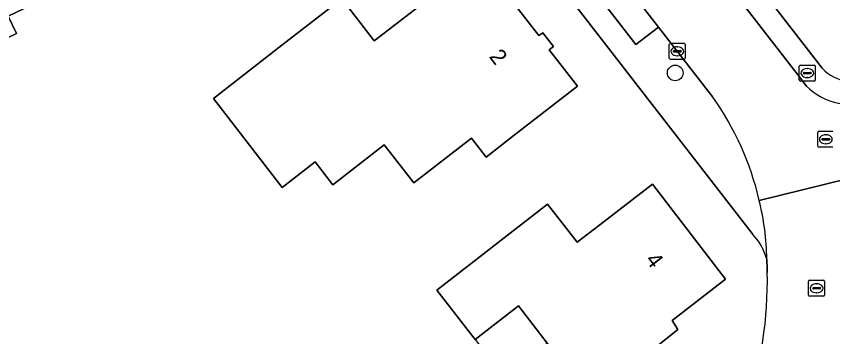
# Model space of a CAD drawing. Extents: x 159499 to 160349, y 382524 to 383273.
# Drawn here: x 159751.6 to 159802.6, y 382906.1 to 382926.1 of the extents above; entities that cross this region are included whole.
import ezdxf

# ---------------------------------------------------------------- set-up
doc = ezdxf.new("R2010")
doc.units = 0
for name, color, linetype in [('IMGEO_Boom', 7, 'Continuous'), ('IMGEO_Brandkraan', 7, 'Continuous'), ('IMGEO_Erf', 7, 'Continuous'), ('IMGEO_Kolk', 7, 'Continuous'), ('IMGEO_Pand', 7, 'Continuous'), ('IMGEO_Pand_nummerreeks', 7, 'Continuous'), ('IMGEO_Pand_overbouw', 7, 'Continuous'), ('IMGEO_Parkeervlak_open', 7, 'Continuous'), ('IMGEO_Rijbaan_lokaal_open', 7, 'Continuous'), ('IMGEO_Rioolput', 7, 'Continuous'), ('IMGEO_Voetpad_open', 7, 'Continuous')]:
    doc.layers.add(name, color=color, linetype=linetype)

msp = doc.modelspace()

# ---------------------------------------------------------------- linework, layer by layer
at = {"layer": 'IMGEO_Boom'}
msp.add_circle((159792.767, 382922.58), 0.489, dxfattribs=at)
at = {"layer": 'IMGEO_Brandkraan'}
for p, q in [((159800.523, 382922.147), (159800.523, 382922.999)), ((159800.598, 382923.073), (159801.45, 382923.073)), ((159800.825, 382922.616), (159801.223, 382922.616)), ((159801.011, 382922.853), (159801.036, 382922.853)), ((159801.524, 382922.999), (159801.524, 382922.147)), ((159800.782, 382922.567), (159800.782, 382922.579)), ((159801.22, 382922.53), (159800.822, 382922.53)), ((159801.034, 382922.293), (159801.009, 382922.293)), ((159801.266, 382922.579), (159801.266, 382922.567)), ((159801.45, 382922.073), (159800.598, 382922.073))]:
    msp.add_line(p, q, dxfattribs=at)
for points in [[(159800.523, 382922.147), (159800.523, 382922.999)], [(159800.598, 382923.073), (159801.45, 382923.073)], [(159801.524, 382922.999), (159801.524, 382922.147)], [(159801.45, 382922.073), (159800.598, 382922.073)]]:
    msp.add_lwpolyline(points, dxfattribs=at)
for centre, radius, start, end in [((159800.6, 382922.997), 0.0765, 91.552, 178.448), ((159800.6, 382922.997), 0.0765, 91.552, 178.448), ((159800.822, 382922.576), 0.0403, 85.8775, 175.7526), ((159801.227, 382922.578), 0.0386, 1.7309, 96.639), ((159801.448, 382922.997), 0.0765, 1.552, 88.448), ((159801.448, 382922.997), 0.0765, 1.552, 88.448), ((159800.6, 382922.149), 0.0765, 181.552, 268.448), ((159800.6, 382922.149), 0.0765, 181.552, 268.448), ((159800.819, 382922.566), 0.0366, 178.938, 274.7102), ((159801.223, 382922.573), 0.043, 264.8664, 352.4533), ((159801.448, 382922.149), 0.0765, 271.552, 358.448), ((159801.448, 382922.149), 0.0765, 271.552, 358.448)]:
    msp.add_arc(centre, radius, start, end, dxfattribs=at)
for centre, major_axis, ratio, start_param, end_param in [((159801.01, 382922.573), (-0.387, 0.002), 0.722429, 4.712389, 7.853982), ((159801.035, 382922.573), (-0.39, 0.002), 0.717154, 1.570796, 4.712389)]:
    msp.add_ellipse(centre, major_axis=major_axis, ratio=ratio, start_param=start_param, end_param=end_param, dxfattribs=at)
at = {"layer": 'IMGEO_Erf'}
for points in [[(159773.929, 382959.054), (159781.987, 382948.65), (159795.756, 382930.872), (159801.595, 382923.334), (159801.952, 382922.871)], [(159797.571, 382912.547), (159772.924, 382944.336), (159765.561, 382953.83), (159760.969, 382951.204), (159750.017, 382945.267), (159739.773, 382940.307), (159729.278, 382935.832), (159728.417, 382938.099), (159719.333, 382934.542), (159720.458, 382931.079), (159730.546, 382899.75), (159741.202, 382899.547), (159744.626, 382889.831), (159753.21, 382866.555), (159754.229, 382863.79), (159753.482, 382863.418), (159757.881, 382849.879), (159758.599, 382850.174), (159770.661, 382815.939), (159788.308, 382822.433), (159800.223, 382826.817), (159778.58, 382886.258)], [(159798.523, 382910.128), (159798.515, 382910.384), (159798.504, 382910.543), (159798.494, 382910.746), (159798.488, 382910.949)]]:
    msp.add_lwpolyline(points, dxfattribs=at)
for points in [[(159751.087, 382926.132), (159751.61, 382925.043), (159746.157, 382922.42), (159744.341, 382926.195), (159743.443, 382925.765), (159741.493, 382929.697), (159743.097, 382930.481), (159740.204, 382936.523), (159747.59, 382940.076), (159748.977, 382937.192), (159749.194, 382936.741), (159748.744, 382936.525), (159750.044, 382933.821), (159753.561, 382935.525), (159755.739, 382931.025), (159756.785, 382928.864)], [(159782.706, 382918.695), (159780.946, 382917.33), (159780.027, 382918.515), (159776.431, 382915.726), (159774.58, 382918.089), (159771.369, 382915.596), (159770.259, 382917.026), (159768.205, 382915.433), (159763.902, 382920.98), (159767.994, 382924.16), (159771.942, 382927.228), (159773.944, 382924.585), (159777.836, 382927.589), (159778.378, 382926.918), (159781.076, 382928.987), (159784.236, 382924.923), (159784.487, 382925.076), (159785.154, 382924.223), (159784.883, 382924.018), (159786.656, 382921.759)], [(159780.26, 382905.936), (159777.868, 382909.009), (159784.784, 382914.376), (159786.645, 382912.012), (159788.06, 382913.101), (159791.354, 382915.635), (159795.905, 382909.71), (159792.571, 382907.124), (159792.921, 382906.556), (159790.798, 382904.856), (159790.348, 382905.404), (159786.989, 382902.813), (159784.766, 382905.702), (159782.968, 382908.036)]]:
    msp.add_lwpolyline(points, close=True, dxfattribs=at)
for centre, radius, start, end in [((159803.794, 382924.566), 2.504, 222.6159, 302.7282), ((159794.87, 382909.935), 3.758, 15.6579, 44.0402), ((159773.358, 382909.643), 25.17, 341.5576, 1.103)]:
    msp.add_arc(centre, radius, start, end, dxfattribs=at)
at = {"layer": 'IMGEO_Kolk'}
for p, q in [((159792.398, 382923.503), (159792.398, 382924.355)), ((159792.473, 382924.429), (159793.325, 382924.429)), ((159792.886, 382924.209), (159792.911, 382924.209)), ((159793.399, 382924.355), (159793.399, 382923.503)), ((159792.657, 382923.923), (159792.657, 382923.935)), ((159793.095, 382923.886), (159792.697, 382923.886)), ((159792.7, 382923.972), (159793.098, 382923.972)), ((159792.909, 382923.649), (159792.884, 382923.649)), ((159793.141, 382923.935), (159793.141, 382923.923)), ((159793.325, 382923.429), (159792.473, 382923.429)), ((159801.102, 382908.71), (159801.102, 382909.562)), ((159801.177, 382909.636), (159802.029, 382909.636)), ((159801.59, 382909.416), (159801.615, 382909.416)), ((159802.103, 382909.562), (159802.103, 382908.71)), ((159801.361, 382909.13), (159801.361, 382909.142)), ((159801.799, 382909.093), (159801.401, 382909.093)), ((159801.404, 382909.179), (159801.802, 382909.179)), ((159801.613, 382908.856), (159801.588, 382908.856)), ((159801.845, 382909.142), (159801.845, 382909.13)), ((159802.029, 382908.636), (159801.177, 382908.636))]:
    msp.add_line(p, q, dxfattribs=at)
for points in [[(159792.398, 382923.503), (159792.398, 382924.355)], [(159792.473, 382924.429), (159793.325, 382924.429)], [(159793.399, 382924.355), (159793.399, 382923.503)], [(159793.325, 382923.429), (159792.473, 382923.429)], [(159801.102, 382908.71), (159801.102, 382909.562)], [(159801.177, 382909.636), (159802.029, 382909.636)], [(159802.103, 382909.562), (159802.103, 382908.71)], [(159802.029, 382908.636), (159801.177, 382908.636)]]:
    msp.add_lwpolyline(points, dxfattribs=at)
for centre, radius, start, end in [((159792.475, 382924.353), 0.0765, 91.552, 178.448), ((159792.475, 382924.353), 0.0765, 91.552, 178.448), ((159793.323, 382924.353), 0.0765, 1.552, 88.448), ((159793.323, 382924.353), 0.0765, 1.552, 88.448), ((159792.697, 382923.932), 0.0403, 85.8775, 175.7526), ((159792.694, 382923.922), 0.0366, 178.938, 274.7102), ((159793.098, 382923.929), 0.043, 264.8664, 352.4533), ((159793.102, 382923.934), 0.0386, 1.7309, 96.639), ((159792.475, 382923.505), 0.0765, 181.552, 268.448), ((159792.475, 382923.505), 0.0765, 181.552, 268.448), ((159793.323, 382923.505), 0.0765, 271.552, 358.448), ((159793.323, 382923.505), 0.0765, 271.552, 358.448), ((159801.179, 382909.56), 0.0765, 91.552, 178.448), ((159801.179, 382909.56), 0.0765, 91.552, 178.448), ((159802.027, 382909.56), 0.0765, 1.552, 88.448), ((159802.027, 382909.56), 0.0765, 1.552, 88.448), ((159801.401, 382909.139), 0.0403, 85.8775, 175.7526), ((159801.398, 382909.129), 0.0366, 178.938, 274.7102), ((159801.802, 382909.136), 0.043, 264.8664, 352.4533), ((159801.806, 382909.141), 0.0386, 1.7309, 96.639), ((159801.179, 382908.712), 0.0765, 181.552, 268.448), ((159801.179, 382908.712), 0.0765, 181.552, 268.448), ((159802.027, 382908.712), 0.0765, 271.552, 358.448), ((159802.027, 382908.712), 0.0765, 271.552, 358.448)]:
    msp.add_arc(centre, radius, start, end, dxfattribs=at)
for centre, major_axis, ratio, start_param, end_param in [((159792.885, 382923.929), (-0.387, 0.002), 0.722429, 4.712389, 7.853982), ((159792.91, 382923.929), (-0.39, 0.002), 0.717154, 1.570796, 4.712389), ((159801.589, 382909.136), (-0.387, 0.002), 0.722429, 4.712389, 7.853982), ((159801.614, 382909.136), (-0.39, 0.002), 0.717154, 1.570796, 4.712389)]:
    msp.add_ellipse(centre, major_axis=major_axis, ratio=ratio, start_param=start_param, end_param=end_param, dxfattribs=at)
at = {"layer": 'IMGEO_Pand'}
for points in [[(159753.561, 382935.525), (159750.044, 382933.821), (159748.744, 382936.525), (159749.194, 382936.741), (159748.977, 382937.192), (159747.59, 382940.076), (159740.204, 382936.523), (159743.097, 382930.481), (159741.493, 382929.697), (159743.443, 382925.765), (159744.341, 382926.195), (159746.157, 382922.42), (159751.61, 382925.043), (159751.087, 382926.132), (159756.785, 382928.864), (159755.739, 382931.025)], [(159786.656, 382921.759), (159784.883, 382924.018), (159785.154, 382924.223), (159784.487, 382925.076), (159784.236, 382924.923), (159781.076, 382928.987), (159778.378, 382926.918), (159777.836, 382927.589), (159773.944, 382924.585), (159771.942, 382927.228), (159767.994, 382924.16), (159763.902, 382920.98), (159768.205, 382915.433), (159770.259, 382917.026), (159771.369, 382915.596), (159774.58, 382918.089), (159776.431, 382915.726), (159780.027, 382918.515), (159780.946, 382917.33), (159782.706, 382918.695)], [(159795.905, 382909.71), (159791.354, 382915.635), (159788.06, 382913.101), (159786.645, 382912.012), (159784.784, 382914.376), (159777.868, 382909.009), (159780.26, 382905.936), (159782.968, 382908.036), (159784.766, 382905.702), (159786.989, 382902.813), (159790.348, 382905.404), (159790.798, 382904.856), (159792.921, 382906.556), (159792.571, 382907.124)]]:
    msp.add_lwpolyline(points, close=True, dxfattribs=at)
at = {"layer": 'IMGEO_Pand_overbouw'}
msp.add_lwpolyline([(159780.26, 382905.936), (159782.065, 382903.608), (159784.766, 382905.702), (159782.968, 382908.036)], close=True, dxfattribs=at)
at = {"layer": 'IMGEO_Parkeervlak_open'}
msp.add_lwpolyline([(159791.73, 382925.438), (159788.374, 382929.763), (159786.972, 382928.673), (159790.31, 382924.361)], close=True, dxfattribs=at)
at = {"layer": 'IMGEO_Rijbaan_lokaal_open'}
for points in [[(159800.976, 382921.759), (159800.442, 382922.436), (159772.631, 382958.244), (159767.273, 382965.143), (159762.986, 382962.489), (159768.351, 382955.571), (159776.548, 382945.002), (159779.911, 382940.672), (159788.374, 382929.763), (159791.73, 382925.438), (159795.119, 382921.069)], [(159781.987, 382948.65), (159773.929, 382959.054), (159772.631, 382958.244), (159800.442, 382922.436), (159800.976, 382921.759)], [(159801.952, 382922.871), (159801.595, 382923.334), (159795.756, 382930.872), (159781.987, 382948.65)], [(159798.017, 382914.622), (159807.664, 382916.991), (159808.536, 382917.335), (159818.738, 382921.356)], [(159807.664, 382916.991), (159798.017, 382914.622)], [(159798.488, 382910.949), (159798.494, 382910.746), (159798.504, 382910.543), (159798.515, 382910.384), (159798.523, 382910.128)]]:
    msp.add_lwpolyline(points, dxfattribs=at)
for centre, radius, start, end in [((159803.794, 382924.566), 2.504, 222.6159, 302.7282), ((159803.714, 382924.467), 3.851, 224.6802, 293.0789), ((159803.714, 382924.467), 3.851, 224.6802, 293.0789), ((159780.337, 382910.55), 18.143, 12.9715, 35.4374), ((159782.468, 382910.761), 16.021, 0.6707, 13.9439), ((159773.358, 382909.643), 25.17, 341.5576, 1.103)]:
    msp.add_arc(centre, radius, start, end, dxfattribs=at)
at = {"layer": 'IMGEO_Rioolput'}
for p, q in [((159801.681, 382918.009), (159801.681, 382918.861)), ((159801.756, 382918.935), (159802.608, 382918.935)), ((159802.169, 382918.715), (159802.194, 382918.715)), ((159801.94, 382918.429), (159801.94, 382918.441)), ((159802.378, 382918.392), (159801.98, 382918.392)), ((159801.983, 382918.478), (159802.381, 382918.478)), ((159802.192, 382918.155), (159802.167, 382918.155)), ((159802.424, 382918.441), (159802.424, 382918.429)), ((159802.608, 382917.935), (159801.756, 382917.935))]:
    msp.add_line(p, q, dxfattribs=at)
for points in [[(159801.681, 382918.009), (159801.681, 382918.861)], [(159801.756, 382918.935), (159802.608, 382918.935)], [(159802.608, 382917.935), (159801.756, 382917.935)]]:
    msp.add_lwpolyline(points, dxfattribs=at)
for centre, radius, start, end in [((159801.758, 382918.859), 0.0765, 91.552, 178.448), ((159801.758, 382918.859), 0.0765, 91.552, 178.448), ((159801.758, 382918.011), 0.0765, 181.552, 268.448), ((159801.758, 382918.011), 0.0765, 181.552, 268.448), ((159801.98, 382918.438), 0.0403, 85.8775, 175.7526), ((159801.977, 382918.428), 0.0366, 178.938, 274.7102), ((159802.381, 382918.435), 0.043, 264.8664, 352.4533), ((159802.385, 382918.44), 0.0386, 1.7309, 96.639)]:
    msp.add_arc(centre, radius, start, end, dxfattribs=at)
for centre, major_axis, ratio, start_param, end_param in [((159802.168, 382918.435), (-0.387, 0.002), 0.722429, 4.712389, 7.853982), ((159802.193, 382918.435), (-0.39, 0.002), 0.717154, 1.570796, 4.712389)]:
    msp.add_ellipse(centre, major_axis=major_axis, ratio=ratio, start_param=start_param, end_param=end_param, dxfattribs=at)
at = {"layer": 'IMGEO_Voetpad_open'}
for points in [[(159768.351, 382955.571), (159765.561, 382953.83), (159772.924, 382944.336), (159797.571, 382912.547)], [(159795.119, 382921.069), (159791.73, 382925.438), (159790.31, 382924.361), (159786.972, 382928.673), (159788.374, 382929.763), (159779.911, 382940.672), (159778.506, 382939.576), (159775.138, 382943.916), (159776.548, 382945.002), (159768.351, 382955.571)]]:
    msp.add_lwpolyline(points, dxfattribs=at)
for centre, radius, start, end in [((159780.337, 382910.55), 18.143, 12.9715, 35.4374), ((159782.468, 382910.761), 16.021, 0.6707, 13.9439), ((159794.87, 382909.935), 3.758, 15.6579, 44.0402)]:
    msp.add_arc(centre, radius, start, end, dxfattribs=at)

# ---------------------------------------------------------------- texts
at = {"layer": 'IMGEO_Pand_nummerreeks'}
for s, rotation, p in [('2', 307.666, (159781.1, 382923.588)), ('4', 307.5285, (159790.861, 382910.894))]:
    msp.add_text(s, height=1, rotation=rotation, dxfattribs=at).set_placement(p)

doc.saveas('drawing.dxf')
